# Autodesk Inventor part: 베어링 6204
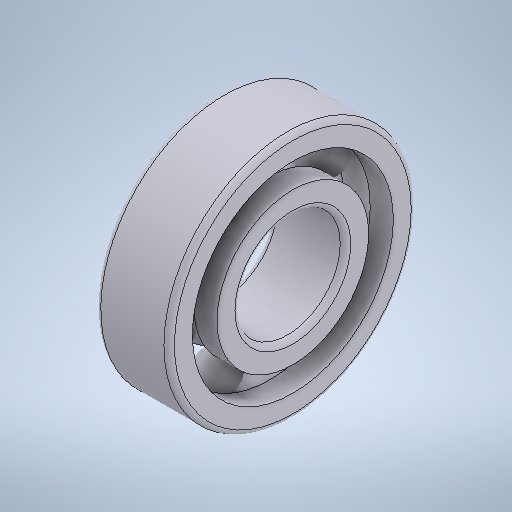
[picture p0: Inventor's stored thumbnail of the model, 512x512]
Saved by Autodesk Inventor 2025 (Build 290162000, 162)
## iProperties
Created: 2024-08
Part Number: 베어링 6204
Material: 강철, 연강
Description: 깊은 그루브 볼 베어링
Document SubType Name: Modeling
Designer: deana
Density: 7.86 g/cm^3
Appearance: 기본값
Author: jhkim
Sending System: Autodesk Inventor 2025
Preprocessor: ST-DEVELOPER v20
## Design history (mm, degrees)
feature "Solid1"
feature "Solid1:1"
feature "Solid1:2"
feature "Solid1:3"
feature "Solid1:4"
feature "Solid1:5"
feature "Solid1:6"
feature "Solid1:7"
feature "Solid1:8"
node "솔리드1"
node "솔리드2"
node "솔리드3"
node "솔리드4"
node "솔리드5"
node "솔리드6"
node "솔리드7"
node "솔리드8"
node "솔리드9"
